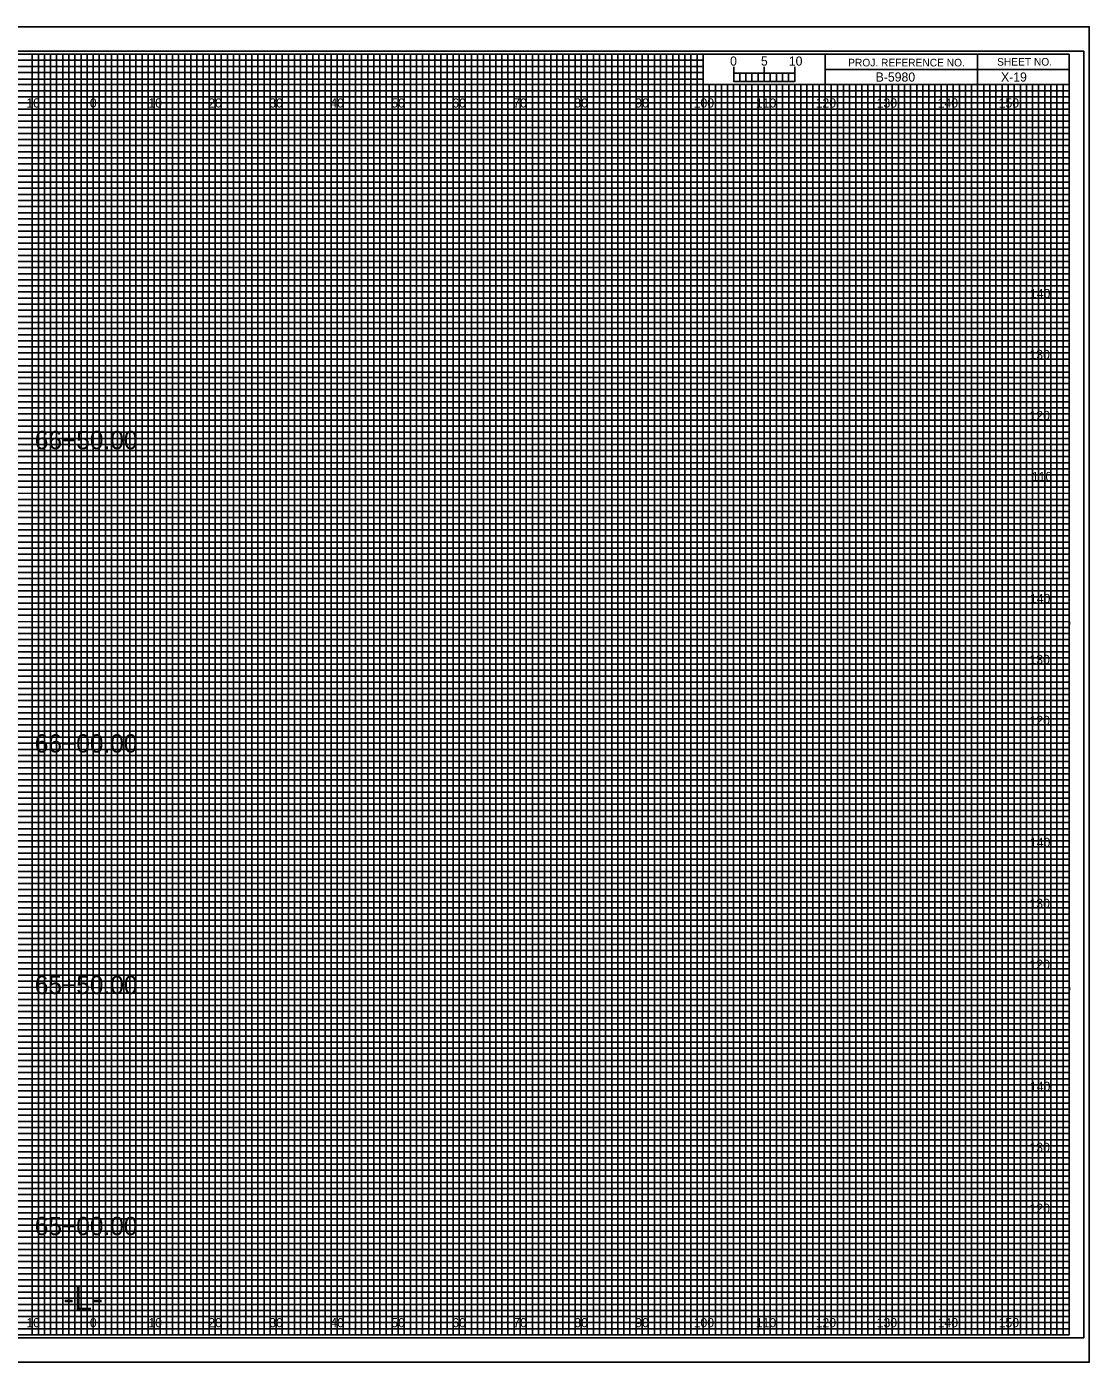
# Model space of a CAD drawing. Extents: x -13 to 323, y -5 to 1754.
# Drawn here: x 149.1 to 323.3, y 655.5 to 874.5 of the extents above; entities that cross this region are included whole.
import ezdxf

# ---------------------------------------------------------------- set-up
doc = ezdxf.new("R2010")
doc.units = 0
for name, color, linetype in [('Exist Cross Section Cell', 7, 'Continuous'), ('Exist XS Center Line Elevation Label', 7, 'Continuous'), ('Exist XS Ground Line', 7, 'Continuous'), ('Prop CMT Bridge Metal Rail', 7, 'Continuous'), ('Prop CMT Pvmt Course 1', 7, 'Continuous'), ('Prop CMT Pvmt Course 2', 7, 'Continuous'), ('Prop CMT Pvmt Course 3', 7, 'Continuous'), ('Prop CMT Pvmt Surface', 7, 'Continuous'), ('Prop CMT Pvmt Surface Shoulder', 7, 'Continuous'), ('Prop CMT Shld Paved Course 1', 7, 'Continuous'), ('Prop CMT Shld Paved Course 2', 7, 'Continuous'), ('Prop CMT Shld Paved Course 3', 7, 'Continuous'), ('Prop CMT Slope Grass', 7, 'Continuous'), ('Prop CMT Subgrade Earthwork', 7, 'Continuous'), ('Prop XS Shear Point Element', 7, 'Continuous'), ('Prop XS Shear Point Label', 7, 'Continuous'), ('Scratch_Level_1', 7, 'Continuous')]:
    doc.layers.add(name, color=color, linetype=linetype)

msp = doc.modelspace()

# ---------------------------------------------------------------- linework, layer by layer
at = {"layer": 'Exist XS Center Line Elevation Label'}
for points in [[(145, 660), (155, 660), (155, 870), (165, 870), (165, 660), (175, 660), (175, 870), (185, 870), (185, 660), (195, 660), (195, 870), (205, 870), (205, 660), (215, 660), (215, 870), (225, 870), (225, 660), (235, 660), (235, 870), (245, 870), (245, 660), (255, 660), (255, 870), (259.93, 870), (260, 870), (260, 865), (264.99, 865), (264.99, 660), (275, 660), (275, 865), (285, 865), (285, 660), (295, 660), (295, 865), (305, 865), (305, 660), (315, 660), (315, 865)], [(0, 865), (275, 865)], [(0, 845), (320, 845), (320, 855), (0, 855)], [(0, 825), (320, 825), (320, 835), (0, 835)], [(0, 805), (320, 805), (320, 815), (0, 815)], [(0, 785), (320, 785), (320, 795), (0, 795)], [(0, 765), (320, 765), (320, 775), (0, 775)], [(0, 745), (320, 745), (320, 755), (0, 755)], [(0, 725), (320, 725), (320, 735), (0, 735)], [(0, 705), (320, 705), (320, 715), (0, 715)], [(0, 685), (320, 685), (320, 695), (0, 695)], [(0, 665), (320, 665), (320, 675), (0, 675)]]:
    msp.add_lwpolyline(points, dxfattribs=at)
at = {"layer": 'Exist XS Ground Line'}
for p, q in [((150, 870), (140, 870)), ((150, 660), (150, 870)), ((170, 870), (160, 870)), ((160, 870), (160, 660)), ((170, 660), (170, 870)), ((190, 870), (180, 870)), ((180, 870), (180, 660)), ((190, 660), (190, 870)), ((210, 870), (200, 870)), ((200, 870), (200, 660)), ((210, 660), (210, 870)), ((230, 870), (220, 870)), ((220, 870), (220, 660)), ((230, 660), (230, 870)), ((250, 870), (240, 870)), ((240, 870), (240, 660)), ((250, 660), (250, 870)), ((260, 870), (260, 660)), ((270, 660), (270, 865)), ((290, 865), (280, 865)), ((280, 865), (280, 660)), ((290, 660), (290, 865)), ((310, 865), (300, 865)), ((300, 865), (300, 660)), ((310, 660), (310, 865)), ((160, 660), (150, 660)), ((180, 660), (170, 660)), ((200, 660), (190, 660)), ((220, 660), (210, 660)), ((240, 660), (230, 660)), ((260, 660), (250, 660)), ((280, 660), (270, 660)), ((300, 660), (290, 660)), ((320, 660), (310, 660)), ((320, 660), (320, 660))]:
    msp.add_line(p, q, dxfattribs=at)
for points in [[(0, 860), (320, 860), (320, 850), (0, 850)], [(0, 840), (320, 840), (320, 830), (0, 830)], [(0, 820), (320, 820), (320, 810), (0, 810)], [(0, 800), (320, 800), (320, 790), (0, 790)], [(0, 780), (320, 780), (320, 770), (0, 770)], [(0, 760), (320, 760), (320, 750), (0, 750)], [(0, 740), (320, 740), (320, 730), (0, 730)], [(0, 720), (320, 720), (320, 710), (0, 710)], [(0, 700), (320, 700), (320, 690), (0, 690)], [(0, 680), (320, 680), (320, 670), (0, 670)]]:
    msp.add_lwpolyline(points, dxfattribs=at)
at = {"layer": 'Prop CMT Pvmt Course 2'}
for p, q in [((265, 865.49), (265, 867.9)), ((265, 866.9), (265, 867.9)), ((270, 865.49), (270, 867.9)), ((275, 865.49), (275, 867.9)), ((275, 866.9), (275, 867.9))]:
    msp.add_line(p, q, dxfattribs=at)
for points in [[(275, 866.9), (265, 866.9), (265, 865.49), (275, 865.49)], [(265, 866.9), (266, 866.9), (266, 865.49), (265, 865.49)], [(267, 866.9), (268, 866.9), (268, 865.49), (267, 865.49)], [(269, 866.9), (270, 866.9), (270, 865.49), (269, 865.49)], [(271, 866.9), (272, 866.9), (272, 865.49), (271, 865.49)], [(273, 866.9), (274, 866.9), (274, 865.49), (273, 865.49)]]:
    msp.add_lwpolyline(points, close=True, dxfattribs=at)
at = {"layer": 'Prop CMT Pvmt Course 3'}
msp.add_lwpolyline([(-13.4, 655.5), (323.3, 655.5), (323.3, 874.5), (-13.4, 874.5)], close=True, dxfattribs=at)
at = {"layer": 'Prop CMT Pvmt Surface'}
for p, q in [((150, 660), (150, 870)), ((160, 660), (160, 870)), ((170, 660), (170, 870)), ((180, 660), (180, 870)), ((190, 660), (190, 870)), ((200, 660), (200, 870)), ((210, 660), (210, 870)), ((220, 660), (220, 870)), ((230, 660), (230, 870)), ((240, 660), (240, 870)), ((250, 660), (250, 870)), ((260, 660), (260, 864.69)), ((270, 660), (270, 864.69)), ((280, 660), (280, 864.69)), ((290, 660), (290, 864.69)), ((300, 660), (300, 864.69)), ((310, 660), (310, 864.69)), ((0, 860), (320, 860)), ((0, 850), (320, 850)), ((0, 840), (320, 840)), ((0, 830), (320, 830)), ((0, 820), (320, 820)), ((0, 810), (320, 810)), ((0, 800), (320, 800)), ((0, 790), (320, 790)), ((0, 780), (320, 780)), ((0, 770), (320, 770)), ((0, 760), (320, 760)), ((0, 750), (320, 750)), ((0, 740), (320, 740)), ((0, 730), (320, 730)), ((0, 720), (320, 720)), ((0, 710), (320, 710)), ((0, 700), (320, 700)), ((0, 690), (320, 690)), ((0, 680), (320, 680)), ((0, 670), (320, 670))]:
    msp.add_line(p, q, dxfattribs=at)
at = {"layer": 'Prop CMT Pvmt Surface Shoulder'}
for p, q in [((323.3, 874.5), (-13.4, 874.5)), ((-13.4, 655.5), (323.3, 655.5))]:
    msp.add_line(p, q, dxfattribs=at)
at = {"layer": 'Prop CMT Shld Paved Course 1'}
for p, q in [((0, 869), (260, 869)), ((260, 867.98), (0, 867.98)), ((260, 869), (260, 867.98)), ((0, 867), (260, 867)), ((260, 865.89), (0, 865.89)), ((260, 867), (260, 865.89)), ((0, 864), (320, 864))]:
    msp.add_line(p, q, dxfattribs=at)
for points in [[(0, 863), (270, 863), (320, 863), (320, 862), (0, 862)], [(0, 861), (320, 861), (320, 859), (0, 859)], [(0, 858), (320, 858), (320, 857), (0, 856.98)], [(0, 856), (320, 856), (320, 854), (0, 854)], [(0, 853), (320, 853), (320, 852), (0, 852)], [(0, 851), (320, 851), (320, 849), (0, 849)], [(0, 848), (320, 848), (320, 847), (0, 847)], [(0, 846), (320, 846), (320, 844), (0, 844)], [(0, 843), (320, 843), (320, 842), (0, 842)], [(0, 841), (320, 841), (320, 839), (0, 839)], [(0, 838), (320, 838), (320, 837), (0, 837)], [(0, 836), (320, 836), (320, 833.95), (320, 833), (320, 832), (0, 832)], [(0, 834), (320, 834), (320, 833), (0, 833)], [(0, 831), (320, 831), (320, 829), (0, 829.03)], [(0, 829.03), (320, 829), (320, 828), (0, 828)], [(0, 827), (320, 827), (320, 826), (0, 826)], [(0, 824), (320, 824), (320, 823), (0, 823)], [(0, 822), (320, 822), (320, 821), (0, 821)], [(-0.07, 818.89), (320, 818.89), (320, 817.88), (-0.07, 817.88)], [(0, 817), (320, 817), (320, 816), (0, 816)], [(0, 814), (320, 814), (320, 813), (0, 813)], [(0, 812), (320, 812), (320, 811), (0, 811)], [(0, 809), (320, 809), (320, 808), (0, 808)], [(0, 807), (320, 807), (320, 806), (0, 806)], [(0, 804), (320, 804), (320, 803), (0, 803)], [(0, 802), (320, 802), (320, 801), (0, 801)], [(0, 799), (320, 799), (319.99, 797.98), (0, 798)], [(0, 797), (320, 797), (320, 796), (0, 796)], [(0, 794), (320, 794), (320, 793), (0, 793)], [(0, 792), (320, 792), (320, 791), (0, 791)], [(0, 789), (320, 789), (320, 788), (0, 788)], [(0, 787), (320, 787), (320, 786), (0, 786)], [(0, 784), (320, 784), (320, 783), (0, 783)], [(0, 782), (320, 782), (320, 781), (0, 781)], [(0, 779), (320, 779), (320, 778), (0, 778)], [(0, 776.99), (320.07, 776.91), (320, 776), (0, 776)], [(0, 774), (320, 774), (320, 773), (0, 773)], [(0, 772), (320, 772), (320, 771), (0, 771)], [(0, 769), (320, 769), (320, 768), (0, 768)], [(0, 767), (320, 767), (320, 766), (0, 766)], [(0, 764), (320, 764), (320, 763), (0, 763)], [(0, 762), (320, 762), (320, 761), (0, 761)], [(0, 759), (320, 759), (320, 758), (0, 758)], [(0, 757), (320, 757), (320, 756), (0, 756)], [(0, 754), (320, 754), (320, 753), (0, 753)], [(0, 752), (320, 752), (320, 751), (0, 751)], [(0, 749), (320, 749), (320, 748), (0, 748)], [(0, 747), (320, 747), (320, 746), (0, 746)], [(0, 744), (320, 744), (320, 743), (0, 743)], [(0, 742), (320, 742), (320, 741), (0, 741)], [(0, 739), (320, 739), (319.99, 737.98), (0, 738)], [(0, 737), (320, 737), (320, 736), (0, 736)], [(0, 734), (320, 734), (320, 733), (0, 733)], [(0, 732), (320, 732), (320, 731), (0, 731)], [(0, 729), (320, 729), (320, 728), (0, 728)], [(0, 727), (320, 727), (320, 726), (0, 726)], [(0, 724), (320, 724), (320, 723), (0, 723)], [(0, 722), (320, 722), (320, 721), (0, 721)], [(0, 719), (320, 719), (320, 718), (0, 718)], [(0, 716.99), (320.07, 716.91), (320, 716), (0, 716)], [(0, 714), (320, 714), (320, 713), (0, 713)], [(0, 712), (320, 712), (320, 711), (0, 711)], [(0, 709), (320, 709), (320, 708), (0, 708)], [(0, 707), (320, 707), (320, 706), (0, 706)], [(0, 704), (320, 704), (320, 703), (0, 703)], [(0, 702), (320, 702), (320, 701), (0, 701)], [(0, 699), (320, 699), (320, 698), (0, 698)], [(0, 697), (320, 697), (320, 696), (0, 696)], [(0, 694), (320, 694), (320, 693), (0, 693)], [(0, 692), (320, 692), (320, 691), (0, 691)], [(0, 689), (320, 689), (320, 688), (0, 688)], [(0, 687), (320, 687), (320, 686), (0, 686)], [(0, 684), (320, 684), (320, 683), (0, 683)], [(0, 682), (320, 682), (320, 681), (0, 681)], [(0, 679), (320, 679), (320, 678), (0, 678)], [(0, 677), (320, 677), (320, 676), (0, 676)], [(0, 674), (320, 674), (320, 673), (0, 673)], [(0, 672), (320, 672), (320, 671), (0, 671)], [(0, 669), (320, 669), (320, 668), (0, 668)], [(0, 667), (320, 667), (320, 666), (0, 666)], [(0, 664), (320, 664), (320, 663), (0, 663)], [(0, 662), (320, 662), (320, 661), (0, 661)]]:
    msp.add_lwpolyline(points, dxfattribs=at)
at = {"layer": 'Prop CMT Shld Paved Course 2'}
for p, q in [((305, 870), (305, 865)), ((305, 865), (305, 870)), ((280, 867.5), (280, 865)), ((320, 867.49), (280, 867.49)), ((280, 865), (320, 865))]:
    msp.add_line(p, q, dxfattribs=at)
for points in [[(320, 870), (0, 870), (0, 660), (320, 660)], [(280, 870), (260, 870), (260, 865.03), (280, 865.03)], [(320, 870), (280, 870), (280, 865), (320, 865)]]:
    msp.add_lwpolyline(points, close=True, dxfattribs=at)
at = {"layer": 'Prop CMT Shld Paved Course 3'}
for p, q in [((267, 865), (266.01, 865)), ((266.01, 865), (266.01, 660)), ((267, 660), (267, 865)), ((269, 865), (268, 865)), ((268, 865), (268, 660)), ((269, 660), (269, 865)), ((266.01, 660), (265, 660)), ((268, 660), (267, 660))]:
    msp.add_line(p, q, dxfattribs=at)
for points in [[(150, 660), (151, 660), (151, 870), (152, 870), (152, 660)], [(152, 660), (153, 660), (153, 870), (154, 870), (154, 660)], [(155, 660), (156, 660), (156, 870), (157, 870), (157, 660)], [(157, 660), (158, 660), (158, 870), (159, 870), (159, 660)], [(160, 660), (161, 660), (161, 870), (162, 870), (162, 660)], [(162, 660), (163, 660), (163, 870), (164, 870), (164, 660)], [(165, 660), (166, 660), (166, 870), (167, 870), (167, 660)], [(167, 660), (168, 660), (168, 870), (169, 870), (169, 660)], [(170, 660), (171, 660), (171, 870), (172, 870), (172, 660)], [(172, 660), (173, 660), (173, 870), (174, 870), (174, 660)], [(175, 660), (176, 660), (176, 870), (177, 870), (177, 660)], [(177, 660), (178, 660), (178, 870), (179, 870), (179, 660)], [(180, 660), (181, 660), (181, 870), (182, 870), (182, 660)], [(182, 660), (183, 660), (183, 870), (184, 870), (184, 660)], [(185, 660), (186, 660), (186, 870), (187, 870), (187, 660)], [(187, 660), (188, 660), (188, 870), (189, 870), (189, 660)], [(190, 660), (191, 660), (191, 870), (192, 870), (192, 660)], [(192, 660), (193, 660), (193, 870), (194, 870), (194, 660)], [(195, 660), (196, 660), (196, 870), (197, 870), (197, 660)], [(197, 660), (198, 660), (198, 870), (199, 870), (199, 660)], [(200, 660), (201, 660), (201, 870), (202, 870), (202, 660)], [(202, 660), (203, 660), (203, 870), (204, 870), (204, 660)], [(205, 660), (206, 660), (206, 870), (207, 870), (207, 660)], [(207, 660), (208, 660), (208, 870), (209, 870), (209, 660)], [(210, 660), (211, 660), (211, 870), (212, 870), (212, 660)], [(212, 660), (213, 660), (213, 870), (214, 870), (214, 660)], [(215, 660), (216, 660), (216, 870), (217, 870), (217, 660)], [(217, 660), (218, 660), (218, 870), (219, 870), (219, 660)], [(220, 660), (221, 660), (221, 870), (222, 870), (222, 660)], [(222, 660), (223, 660), (223, 870), (224, 870), (224, 660)], [(225, 660), (226, 660), (226, 870), (227, 870), (227, 660)], [(227, 660), (228, 660), (228, 870), (229, 870), (229, 660)], [(230, 660), (231, 660), (231, 870), (232, 870), (232, 660)], [(232, 660), (233, 660), (233, 870), (234, 870), (234, 660)], [(235, 660), (236, 660), (236, 870), (237, 870), (237, 660)], [(237, 660), (238, 660), (238, 870), (239, 870), (239, 660)], [(240, 660), (241, 660), (241, 870), (242, 870), (242, 660)], [(242, 660), (243, 660), (243, 870), (244, 870), (244, 660)], [(245, 660), (246, 660), (246, 870), (247, 870), (247, 660)], [(247, 660), (248, 660), (248, 870), (249, 870), (249, 660)], [(250, 660), (251, 660), (251, 870), (252, 870), (252, 660)], [(252, 660), (253, 660), (253, 870), (254, 870), (254, 660)], [(255, 660), (256, 660), (256, 870), (257, 870), (257, 660)], [(257, 660), (258, 660), (258, 870), (259, 870), (259, 660)], [(260, 660), (261, 660), (261, 865), (262.02, 865), (262.02, 660)], [(262, 660), (263, 660), (263, 865), (263.99, 865), (263.99, 660)], [(270, 660), (270.98, 660), (270.98, 865), (272, 865), (272, 660)], [(272, 660), (273, 660), (273, 865), (274.05, 865), (274.05, 660)], [(275, 660), (276, 660), (276, 865), (277, 865), (277, 660)], [(277, 660), (278, 660), (278, 865), (279, 865), (279, 660)], [(280, 660), (281, 660), (281, 865), (282, 865), (282, 660)], [(282, 660), (283, 660), (283, 865), (284, 865), (284, 660)], [(285, 660), (286, 660), (286, 865), (287, 865), (287, 660)], [(287, 660), (288, 660), (288, 865), (289, 865), (289, 660)], [(290, 660), (291, 660), (291, 865), (292, 865), (292, 660)], [(292, 660), (293, 660), (293, 865), (294, 865), (294, 660)], [(295, 660), (296, 660), (296, 865), (297, 865), (297, 660)], [(297, 660), (298, 660), (298, 865), (299, 865), (299, 660)], [(300, 660), (301, 660), (301, 865), (302, 865), (302, 660)], [(302, 660), (303, 660), (303, 865), (304, 865), (304, 660)], [(305, 660), (306, 660), (306, 865), (307, 865), (307, 660)], [(307, 660), (308, 660), (308, 865), (309, 865), (309, 660)], [(310, 660), (311, 660), (311, 865), (312, 865), (312, 660)], [(312, 660), (313, 660), (313, 865), (314, 865), (314, 660)], [(315, 660), (316, 660), (316, 865), (317, 865), (317, 660)], [(317, 660), (318, 660), (318, 865), (319, 865), (319, 660)]]:
    msp.add_lwpolyline(points, dxfattribs=at)
at = {"layer": 'Prop CMT Subgrade Earthwork'}
msp.add_lwpolyline([(-10.8, 659.5), (322.4, 659.5), (322.4, 870.5), (-10.8, 870.5)], close=True, dxfattribs=at)

# ---------------------------------------------------------------- texts
at = {"layer": 'Exist Cross Section Cell'}
for s, p in [('10', (149.04, 861.25)), ('0', (159.45, 861.25)), ('0', (159.45, 861.25)), ('10', (169.04, 861.25)), ('20', (178.86, 861.25)), ('30', (188.86, 861.25)), ('40', (198.86, 861.25)), ('50', (208.86, 861.25)), ('60', (218.86, 861.25)), ('70', (228.86, 861.25)), ('80', (238.86, 861.25)), ('90', (248.86, 861.25)), ('100', (258.44, 861.25)), ('110', (268.62, 861.25)), ('120', (278.44, 861.25)), ('130', (288.44, 861.25)), ('140', (298.44, 861.25)), ('150', (308.44, 861.25)), ('10', (149.04, 661.25)), ('0', (159.45, 661.25)), ('0', (159.45, 661.25)), ('10', (169.04, 661.25)), ('20', (178.86, 661.25)), ('30', (188.86, 661.25)), ('40', (198.86, 661.25)), ('50', (208.86, 661.25)), ('60', (218.86, 661.25)), ('70', (228.86, 661.25)), ('80', (238.86, 661.25)), ('90', (248.86, 661.25)), ('100', (258.44, 661.25)), ('110', (268.62, 661.25)), ('120', (278.44, 661.25)), ('130', (288.44, 661.25)), ('140', (298.44, 661.25)), ('150', (308.44, 661.25))]:
    msp.add_text(s, height=1.5, dxfattribs=at).set_placement(p)
at = {"layer": 'Prop CMT Bridge Metal Rail'}
for s, p in [('5', (269.47, 868.12)), ('10', (274.04, 868.12))]:
    msp.add_text(s, height=1.5, dxfattribs=at).set_placement(p)
at = {"layer": 'Prop CMT Pvmt Course 1'}
for s, p in [('140', (313.57, 830)), ('130', (313.49, 820)), ('120', (313.5, 810)), ('110', (313.88, 800)), ('140', (313.57, 780)), ('130', (313.49, 770)), ('120', (313.5, 760)), ('140', (313.57, 740)), ('130', (313.49, 730)), ('120', (313.5, 720)), ('140', (313.57, 700)), ('130', (313.49, 690)), ('120', (313.5, 680))]:
    msp.add_text(s, height=1.5, dxfattribs=at).set_placement(p)
at = {"layer": 'Prop CMT Pvmt Course 2'}
msp.add_text('0', height=1.5, dxfattribs=at).set_placement((264.41, 868.12))
at = {"layer": 'Prop CMT Shld Paved Course 2'}
for s, p in [('PROJ. REFERENCE NO.', (283.77, 867.99)), ('SHEET NO.', (308.19, 868.12))]:
    msp.add_text(s, height=1.25, dxfattribs=at).set_placement(p)
at = {"layer": 'Prop CMT Slope Grass'}
for s, p in [('66+50.00', (150.41, 805.22)), ('66+00.00', (150.41, 755.48)), ('65+50.00', (150.41, 715.88)), ('65+00.00', (150.41, 676.35))]:
    msp.add_text(s, height=3, dxfattribs=at).set_placement(p)
at = {"layer": 'Prop XS Shear Point Element'}
msp.add_text('-L-', height=4, dxfattribs=at).set_placement((155.06, 664))
at = {"layer": 'Prop XS Shear Point Label'}
msp.add_text('B-5980', height=1.5, dxfattribs=at).set_placement((288.28, 865.5))
at = {"layer": 'Scratch_Level_1'}
msp.add_text('X-19', height=1.5, dxfattribs=at).set_placement((308.83, 865.5))

doc.saveas('drawing.dxf')
